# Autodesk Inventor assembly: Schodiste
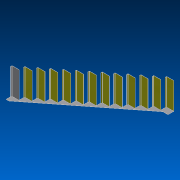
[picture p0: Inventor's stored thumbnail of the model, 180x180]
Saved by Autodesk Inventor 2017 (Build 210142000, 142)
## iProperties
Part Number: Schodiste
Material: Všeobecné
Document SubType Name: Assembly
Designer: navara
Author: navara
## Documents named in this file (3)
- D:\Dokumenty\CAD_DATA\Inventor_2017\Projekty\Soucastky_2017\20170714\Schodiste.iam
- D:\Dokumenty\CAD_DATA\Inventor_2015\Projekty\SOUCASTKY_2015\20161013\SchodisteBok.ipt
- D:\Dokumenty\CAD_DATA\Inventor_2015\Projekty\SOUCASTKY_2015\20161013\Schodiste.ipt
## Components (2 placed, 2 different names)
1. SchodisteBok:1
2. Schodiste:1
